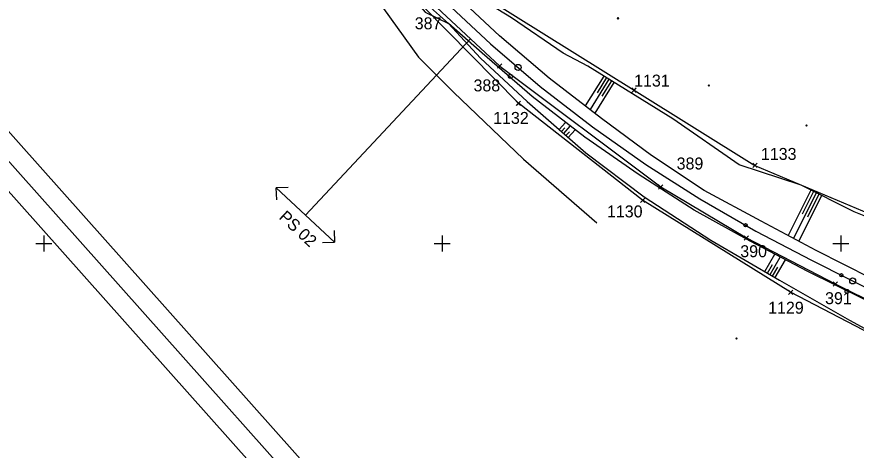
# Model space of a CAD drawing. Extents: x -866402 to -860377, y -1041908 to -1038598.
# Drawn here: x -865406.8 to -865196.1, y -1040251.9 to -1040143.1 of the extents above; entities that cross this region are included whole.
import ezdxf

# ---------------------------------------------------------------- set-up
doc = ezdxf.new("R2010")
doc.units = 0
for name, color, linetype in [('PS 02 trasa', 7, 'Continuous'), ('SZDC', 7, 'Continuous'), ('Vrstva 1', 7, 'Continuous'), ('Vrstva 48', 7, 'Continuous'), ('Vrstva 49', 7, 'Continuous'), ('Vrstva 5', 7, 'Continuous'), ('Vrstva 60', 7, 'Continuous'), ('Vrstva 7', 7, 'Continuous')]:
    doc.layers.add(name, color=color, linetype=linetype)

msp = doc.modelspace()

# ---------------------------------------------------------------- linework, layer by layer
at = {"layer": 'PS 02 trasa'}
for p, q in [((-865334.35, -1040192.85), (-865292.88, -1040148.59)), ((-865338.65, -1040185.91), (-865341.65, -1040186.01)), ((-865341.65, -1040186.01), (-865334.35, -1040192.85)), ((-865341.55, -1040189.01), (-865341.65, -1040186.01)), ((-865327.05, -1040199.68), (-865334.35, -1040192.85)), ((-865327.15, -1040196.69), (-865327.05, -1040199.68)), ((-865330.05, -1040199.78), (-865327.05, -1040199.68))]:
    msp.add_line(p, q, dxfattribs=at)
msp.add_lwpolyline([(-865392.51, -1039988.18), (-865384.79, -1040012.1), (-865375.47, -1040034.61), (-865375.81, -1040037.34), (-865373.72, -1040041.97), (-865371.03, -1040043.48), (-865363.71, -1040057.88), (-865350.96, -1040079.61), (-865347, -1040089.4), (-865342.71, -1040092.36), (-865339.34, -1040096.65), (-865338.45, -1040097.8), (-865338.12, -1040102.62), (-865335.84, -1040105.75), (-865330.4, -1040108.23), (-865329.96, -1040108.8), (-865320.81, -1040120.03), (-865303.74, -1040138.41), (-865285.56, -1040155.45), (-865245.16, -1040185.8), (-865223.67, -1040198.6), (-865201.38, -1040210.15), (-865178.79, -1040221.3)], dxfattribs=at)
at = {"layer": 'SZDC'}
for points in [[(-865157.46, -1040240.87), (-865212.59, -1040212.22), (-865249.71, -1040189.15), (-865280.87, -1040164.78), (-865316.58, -1040128.46), (-865344.65, -1040099.41), (-865367.45, -1040089.25), (-865388.85, -1040062.62), (-865389.06, -1040061.16), (-865371.42, -1040053.29), (-865375.06, -1040047.83), (-865388.7, -1040026.25), (-865395.62, -1040020.69), (-865413.96, -1039944.15)], [(-865381.32, -1039975.48), (-865364.16, -1040003.66), (-865343.47, -1040025.47), (-865358.93, -1040046.69), (-865347.26, -1040054.41), (-865337.46, -1040076.98), (-865333.56, -1040085.78), (-865314.1, -1040109.68), (-865297.21, -1040133.13), (-865251.84, -1040161.5), (-865221.54, -1040180.39), (-865167.51, -1040203.13), (-865136.9, -1040220.12), (-865121.09, -1040243.74), (-865091.16, -1040253.56), (-865065.24, -1040268.27), (-865053.91, -1040285.28), (-865043.13, -1040305.31), (-865029.04, -1040320.43), (-865023.67, -1040361.98), (-865022.71, -1040375.04), (-865013.7, -1040387.94)]]:
    msp.add_lwpolyline(points, dxfattribs=at)
at = {"layer": 'Vrstva 1'}
for points in [[(-865732.63, -1039823.16), (-864894.8, -1040764.23), (-864672.98, -1040566.75), (-865510.81, -1039625.68)], [(-865511.22, -1039632.74), (-864680.04, -1040566.34), (-864894.39, -1040757.18), (-865725.57, -1039823.57)], [(-865718.52, -1039823.98), (-865030.3, -1040597.01), (-864823.41, -1040412.82), (-865511.63, -1039639.79)], [(-865511.63, -1039639.79), (-864823.41, -1040412.82), (-865030.3, -1040597.01), (-865718.52, -1039823.98)]]:
    msp.add_lwpolyline(points, close=True, dxfattribs=at)
for points in [[(-865386.82, -1039997.88), (-865381.07, -1040014.14), (-865374.75, -1040029.59), (-865370.06, -1040039.85), (-865362.07, -1040055.65), (-865353.41, -1040070.79), (-865344.07, -1040085.35), (-865337.61, -1040094.66), (-865332.64, -1040101.38), (-865322.83, -1040113.67), (-865311.88, -1040126.14), (-865300.18, -1040138.31), (-865287.88, -1040149.9), (-865275.39, -1040160.56), (-865262.26, -1040170.74), (-865248.91, -1040180.15), (-865235.39, -1040188.79), (-865221.26, -1040196.9), (-865207.35, -1040204.18), (-865197.91, -1040208.93)], [(-865197.91, -1040208.93), (-865193.4, -1040211.18), (-865165.29, -1040225.16)]]:
    msp.add_lwpolyline(points, dxfattribs=at)
for centre in [(-865223.87, -1040195.41), (-865199.83, -1040207.96)]:
    msp.add_circle(centre, 0.4, dxfattribs=at)
at = {"layer": 'Vrstva 48'}
for p, q in [((-865259.45, -1040157.96), (-865264.1, -1040165.46)), ((-865258.18, -1040158.75), (-865262.9, -1040166.39)), ((-865256.9, -1040159.54), (-865261.71, -1040167.31)), ((-865258.81, -1040158.35), (-865261.16, -1040162.14)), ((-865257.54, -1040159.14), (-865259.92, -1040162.99)), ((-865270.64, -1040171.4), (-865269.05, -1040169.59)), ((-865269.51, -1040172.39), (-865267.86, -1040170.51)), ((-865270.08, -1040171.9), (-865269.26, -1040170.97)), ((-865268.95, -1040172.89), (-865268.1, -1040171.93)), ((-865268.38, -1040173.38), (-865266.67, -1040171.43)), ((-865207.5, -1040186.61), (-865213.19, -1040198.02)), ((-865206.16, -1040187.28), (-865211.86, -1040198.72)), ((-865206.83, -1040186.95), (-865209.68, -1040192.66)), ((-865205.49, -1040187.62), (-865208.34, -1040193.35)), ((-865204.82, -1040187.95), (-865210.54, -1040199.43)), ((-865219.03, -1040207.05), (-865216.51, -1040202.7)), ((-865217.74, -1040207.8), (-865215.18, -1040203.4)), ((-865216.44, -1040208.55), (-865213.85, -1040204.1)), ((-865218.39, -1040207.42), (-865217.12, -1040205.24)), ((-865217.09, -1040208.18), (-865215.8, -1040205.96))]:
    msp.add_line(p, q, dxfattribs=at)
at = {"layer": 'Vrstva 49'}
for p, q in [((-865256.06, -1040143.25), (-865255.71, -1040143.6)), ((-865256.06, -1040143.6), (-865255.71, -1040143.25)), ((-865233.3, -1040160.13), (-865232.95, -1040160.49)), ((-865233.3, -1040160.49), (-865232.95, -1040160.13)), ((-865208.74, -1040170.18), (-865208.39, -1040170.53)), ((-865208.74, -1040170.53), (-865208.39, -1040170.18)), ((-865226.36, -1040223.64), (-865226.01, -1040223.99)), ((-865226.36, -1040223.99), (-865226.01, -1040223.64))]:
    msp.add_line(p, q, dxfattribs=at)
for points in [[(-865298.43, -1040144.73), (-865302.95, -1040140.74), (-865314.35, -1040127.91), (-865325.23, -1040115.11), (-865335.2, -1040102.84), (-865338.93, -1040099.66), (-865350.23, -1040092.05)], [(-865336.58, -1040106.43), (-865325.47, -1040119), (-865311.89, -1040133.04), (-865304.29, -1040141.89), (-865298.43, -1040144.73)], [(-865120.07, -1040245.4), (-865133, -1040227.16), (-865149.54, -1040213.53), (-865167.8, -1040203.55), (-865196.59, -1040192.05), (-865209.96, -1040185.39), (-865225.52, -1040180.24), (-865242.16, -1040168.66), (-865263.47, -1040155.47), (-865269.65, -1040152.18), (-865282.63, -1040143.33), (-865297.15, -1040134.4), (-865306.55, -1040120.68)], [(-865323.93, -1040128.1), (-865305.94, -1040153.24), (-865297.14, -1040162.01), (-865279.62, -1040178.81), (-865261.21, -1040194.81)], [(-865122.3, -1040244.83), (-865136.42, -1040236.91), (-865150, -1040229.66), (-865164.28, -1040222.95), (-865192.27, -1040208.77), (-865206.2, -1040201.73), (-865219.98, -1040194.42), (-865234.23, -1040186.65), (-865247.46, -1040177.9), (-865260.06, -1040168.59), (-865273.13, -1040158.48), (-865285.59, -1040147.84), (-865298.1, -1040136.14)], [(-865298.43, -1040144.73), (-865290.36, -1040153.46), (-865278.7, -1040164.32), (-865263.96, -1040177.27), (-865249.36, -1040188.31), (-865232.62, -1040199.15), (-865215.4, -1040209.16), (-865197.81, -1040219.26), (-865179.25, -1040229.4), (-865167.55, -1040234.18), (-865152.17, -1040241.51)], [(-865208.27, -1040207.04), (-865222.76, -1040199.42), (-865236.8, -1040191.59), (-865250.86, -1040182.61), (-865264.25, -1040173.28), (-865277.45, -1040163.12), (-865289.98, -1040152.22), (-865298.43, -1040144.73)], [(-865128.42, -1040249.11), (-865129.57, -1040247.66), (-865139.14, -1040242.25), (-865152.53, -1040234.94), (-865166.3, -1040227.46), (-865194.4, -1040213.85), (-865208.27, -1040207.04)]]:
    msp.add_lwpolyline(points, dxfattribs=at)
at = {"layer": 'Vrstva 5'}
for p, q in [((-865400, -1040198), (-865400, -1040202)), ((-865300, -1040198), (-865300, -1040202)), ((-865200, -1040198), (-865200, -1040202)), ((-865402, -1040200), (-865398, -1040200)), ((-865302, -1040200), (-865298, -1040200)), ((-865202, -1040200), (-865198, -1040200))]:
    msp.add_line(p, q, dxfattribs=at)
at = {"layer": 'Vrstva 60'}
for p, q in [((-865285.11, -1040155.9), (-865286.11, -1040154.9)), ((-865285.11, -1040155), (-865286.11, -1040156)), ((-865286.01, -1040155.9), (-865285.01, -1040154.9)), ((-865286.01, -1040155), (-865285.01, -1040156)), ((-865285.56, -1040155.45), (-865285.56, -1040155.45)), ((-865251.39, -1040161.95), (-865252.39, -1040160.95)), ((-865251.39, -1040161.05), (-865252.39, -1040162.05)), ((-865252.29, -1040161.95), (-865251.29, -1040160.95)), ((-865252.29, -1040161.05), (-865251.29, -1040162.05)), ((-865251.84, -1040161.5), (-865251.84, -1040161.5)), ((-865280.42, -1040165.23), (-865281.42, -1040164.23)), ((-865280.42, -1040164.33), (-865281.42, -1040165.33)), ((-865281.32, -1040165.23), (-865280.32, -1040164.23)), ((-865281.32, -1040164.33), (-865280.32, -1040165.33)), ((-865280.87, -1040164.78), (-865280.87, -1040164.78)), ((-865221.09, -1040180.84), (-865222.09, -1040179.84)), ((-865221.09, -1040179.94), (-865222.09, -1040180.94)), ((-865221.99, -1040180.84), (-865220.99, -1040179.84)), ((-865221.99, -1040179.94), (-865220.99, -1040180.94)), ((-865221.54, -1040180.39), (-865221.54, -1040180.39)), ((-865244.71, -1040186.25), (-865245.71, -1040185.25)), ((-865244.71, -1040185.35), (-865245.71, -1040186.35)), ((-865245.61, -1040186.25), (-865244.61, -1040185.25)), ((-865245.61, -1040185.35), (-865244.61, -1040186.35)), ((-865245.16, -1040185.8), (-865245.16, -1040185.8)), ((-865249.26, -1040189.6), (-865250.26, -1040188.6)), ((-865249.26, -1040188.7), (-865250.26, -1040189.7)), ((-865250.16, -1040189.6), (-865249.16, -1040188.6)), ((-865250.16, -1040188.7), (-865249.16, -1040189.7)), ((-865249.71, -1040189.15), (-865249.71, -1040189.15)), ((-865223.22, -1040199.05), (-865224.22, -1040198.05)), ((-865223.22, -1040198.15), (-865224.22, -1040199.15)), ((-865224.12, -1040199.05), (-865223.12, -1040198.05)), ((-865224.12, -1040198.15), (-865223.12, -1040199.15)), ((-865223.67, -1040198.6), (-865223.67, -1040198.6)), ((-865200.93, -1040210.6), (-865201.93, -1040209.6)), ((-865200.93, -1040209.7), (-865201.93, -1040210.7)), ((-865201.83, -1040210.6), (-865200.83, -1040209.6)), ((-865201.83, -1040209.7), (-865200.83, -1040210.7)), ((-865201.38, -1040210.15), (-865201.38, -1040210.15)), ((-865212.14, -1040212.67), (-865213.14, -1040211.67)), ((-865212.14, -1040211.77), (-865213.14, -1040212.77)), ((-865213.04, -1040212.67), (-865212.04, -1040211.67)), ((-865213.04, -1040211.77), (-865212.04, -1040212.77)), ((-865212.59, -1040212.22), (-865212.59, -1040212.22))]:
    msp.add_line(p, q, dxfattribs=at)
at = {"layer": 'Vrstva 7'}
for p, q in [((-865282.95, -1040158.05), (-865282.85, -1040158.05)), ((-865198.46, -1040212.02), (-865198.36, -1040212.02))]:
    msp.add_line(p, q, dxfattribs=at)
for centre, radius in [((-865280.98, -1040155.79), 0.75), ((-865282.9, -1040158.05), 0.5), ((-865197, -1040209.39), 0.75), ((-865198.41, -1040212.02), 0.5)]:
    msp.add_circle(centre, radius, dxfattribs=at)

# ---------------------------------------------------------------- texts
at = {"layer": 'PS 02 trasa'}
msp.add_text('PS 02', height=3, rotation=316.8652, dxfattribs=at).set_placement((-865341.19, -1040193.63))
at = {"layer": 'Vrstva 60'}
for s, p in [('387', (-865306.9, -1040146.22)), ('1131', (-865251.84, -1040160.6)), ('388', (-865292.15, -1040161.81)), ('1132', (-865287.22, -1040169.97)), ('1133', (-865220.02, -1040179.01)), ('389', (-865241.17, -1040181.41)), ('1130', (-865258.66, -1040193.44)), ('390', (-865225.2, -1040203.43)), ('391', (-865203.92, -1040215.22)), ('1129', (-865218.21, -1040217.61))]:
    msp.add_text(s, height=3, dxfattribs=at).set_placement(p)

doc.saveas('drawing.dxf')
